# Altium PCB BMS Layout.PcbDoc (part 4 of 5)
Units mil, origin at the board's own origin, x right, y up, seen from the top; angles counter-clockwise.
Board outline 5576.78 x 4051.82 mil, 6 copper layers (Top Layer, GND1, Analog Signal, Power, GND2, Bottom Layer), stack 61.2 mil thick; 425 components, 206 nets, 1164 pads, 390 vias.
Unrouted connection lines stored in the file: 32.
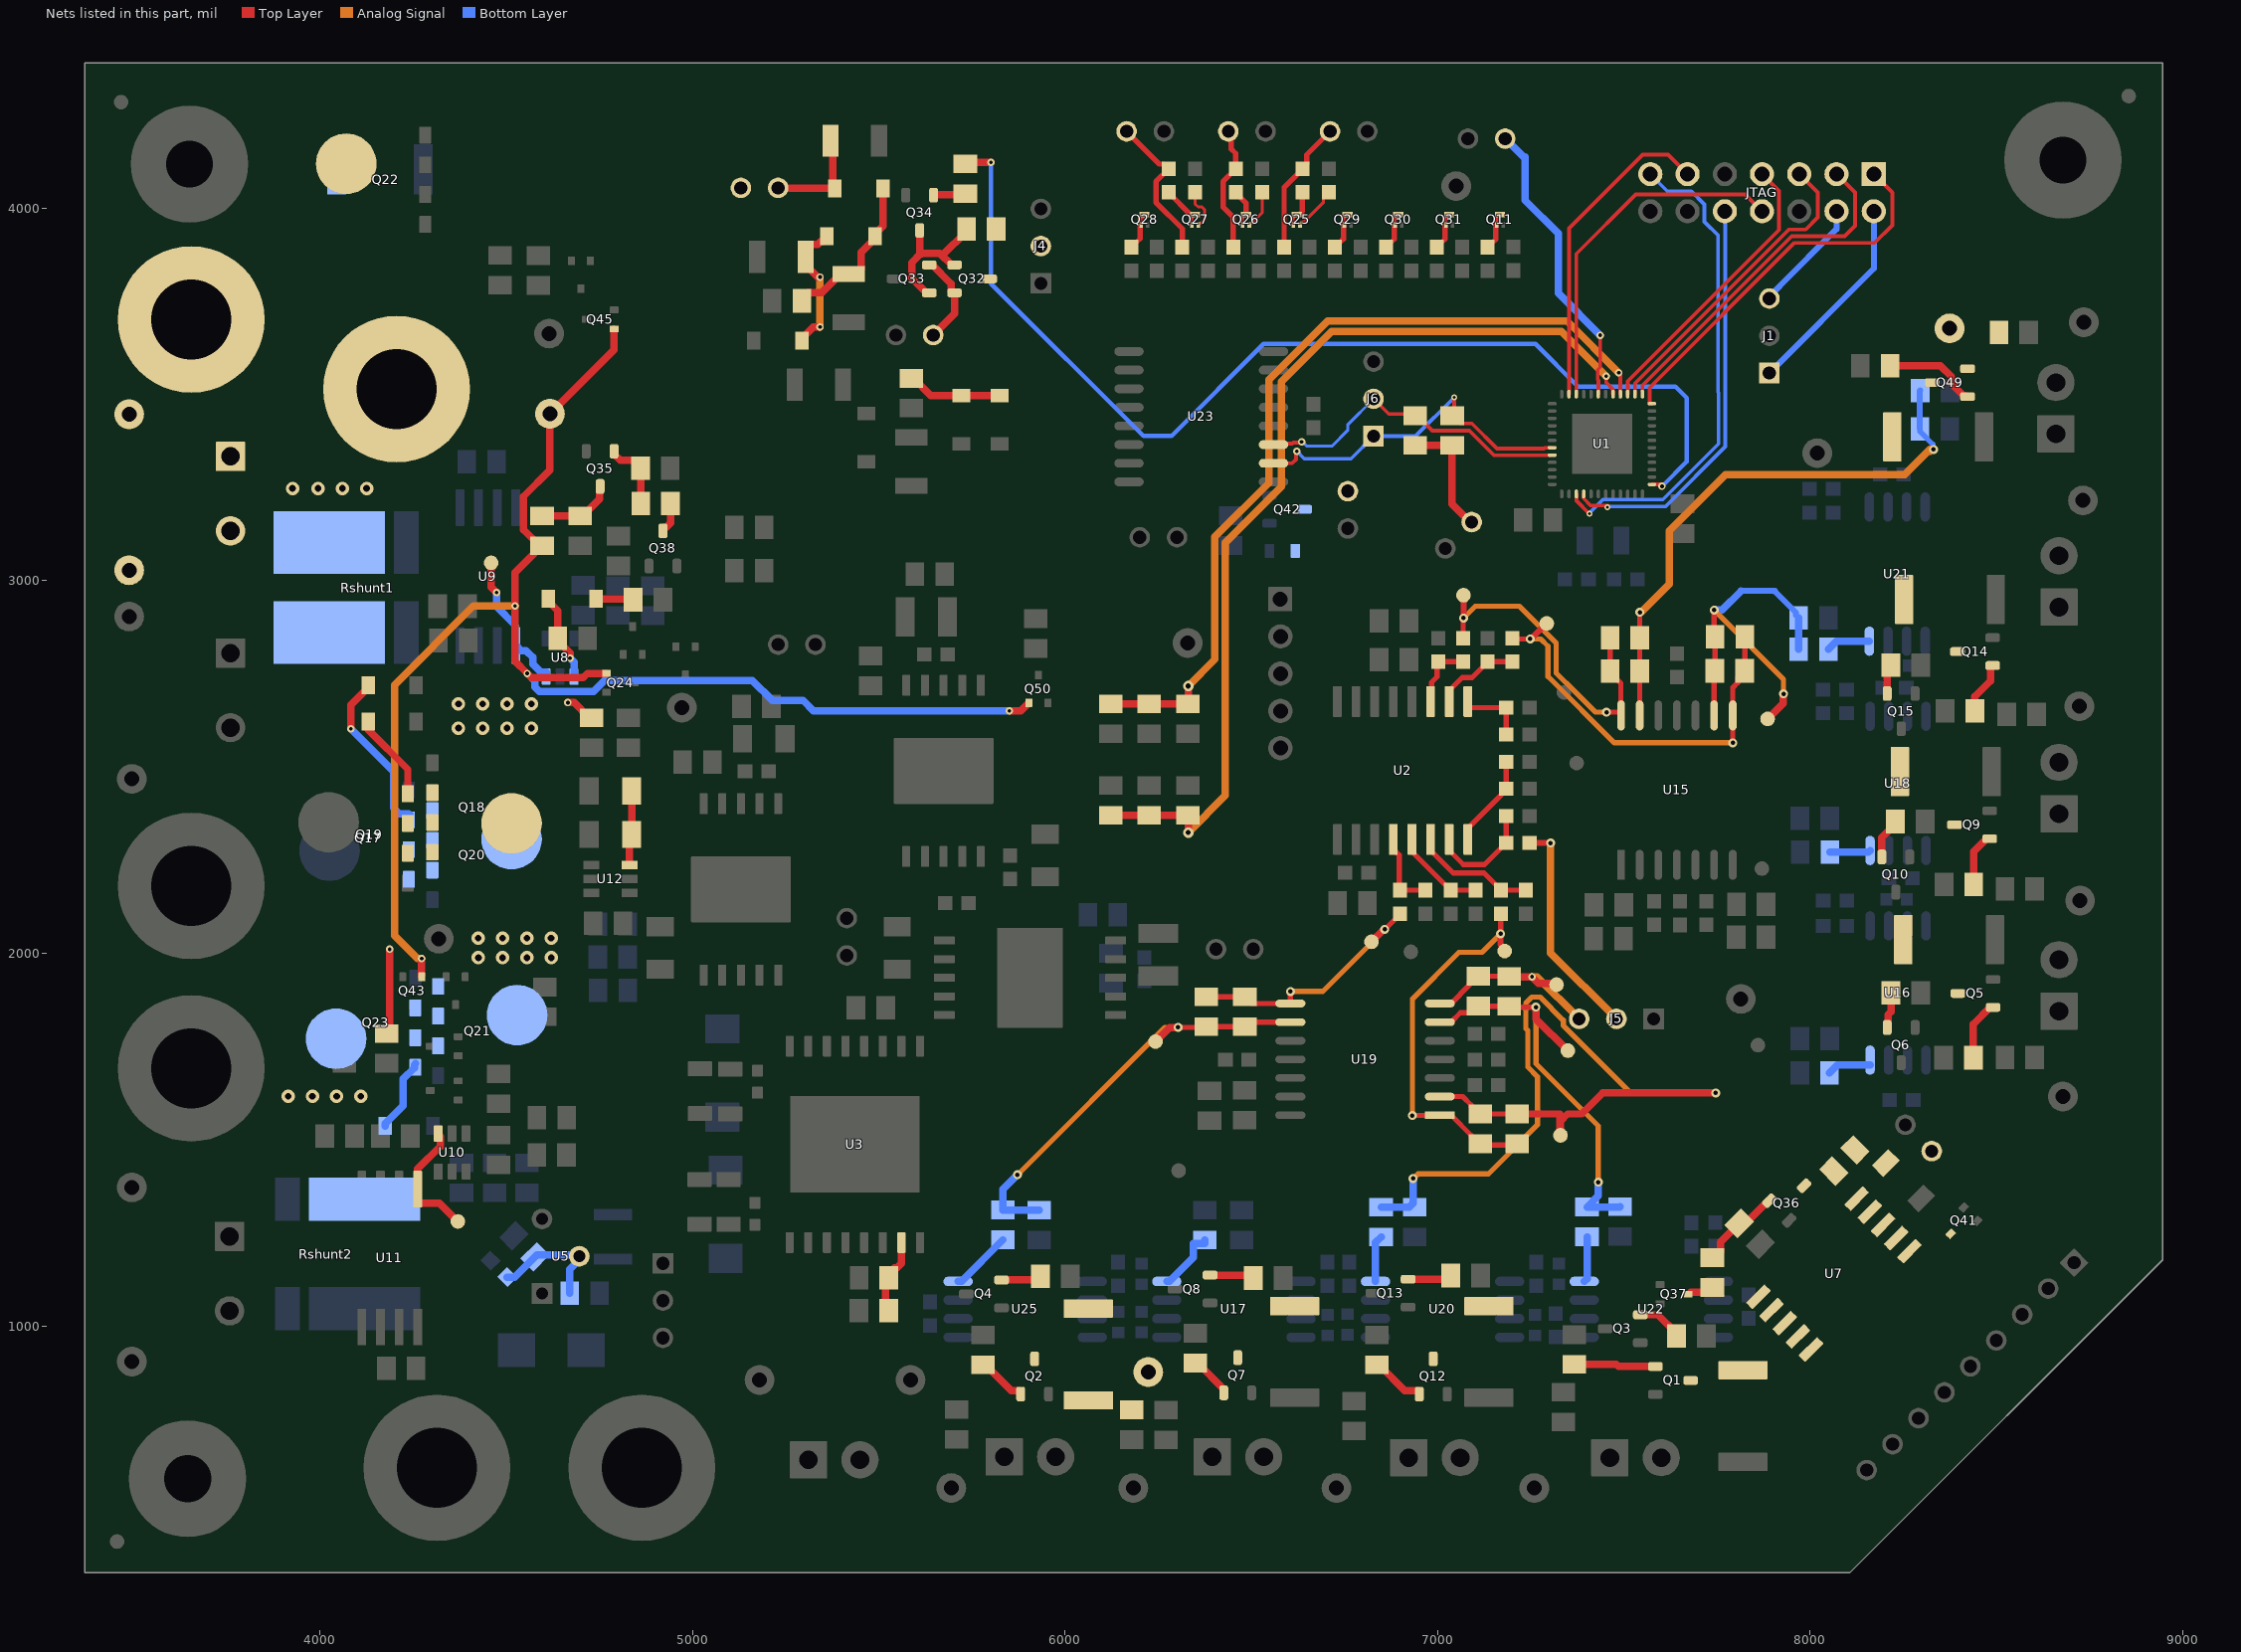
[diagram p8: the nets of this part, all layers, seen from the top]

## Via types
v1: diameter 20, hole 10, Top Layer to Bottom Layer, tented both sides, 113 vias
v2: diameter 24, hole 12, Top Layer to Bottom Layer, tented both sides, 103 vias
v3: diameter 19.68, hole 7.87, Top Layer to Bottom Layer, 93 vias
v4: diameter 36, hole 18, Top Layer to Bottom Layer, 46 vias
v5: diameter 36, hole 18, Top Layer to Bottom Layer, tented both sides, 12 vias
v6: diameter 16, hole 8, Top Layer to Bottom Layer, tented both sides, 10 vias
v7: diameter 26, hole 13, Top Layer to Bottom Layer, tented both sides, 7 vias
v8: diameter 32, hole 16, Top Layer to Bottom Layer, tented both sides, 3 vias
v9: diameter 28, hole 14, Top Layer to Bottom Layer, tented both sides, 2 vias
v10: diameter 20, hole 12, Top Layer to Bottom Layer, tented both sides, 1 vias

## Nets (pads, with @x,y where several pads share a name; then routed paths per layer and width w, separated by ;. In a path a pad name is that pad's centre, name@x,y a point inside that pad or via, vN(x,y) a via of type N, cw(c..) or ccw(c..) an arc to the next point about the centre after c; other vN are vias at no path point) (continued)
NetC93_1: C93.1 R93.2 R95.1 TP14.1 U19.1 | length 1047.4
  Top Layer w14: v2(6932.25,1564.33) 6932.71,1564.8 7005.32,1564.8 U19.1@7005.79,1565.26 7035.92,1565.26 7090.41,1510.77 7090.41,1506.75 7108.41,1488.75 C93.1@7114.91,1488.75 7118.22,1485.45 7213.11,1485.45 R93.2@7213.11,1488.75 ; v2(7168.77,2052.18) 7169.25,2052.66 7169.25,2105.82 R95.1@7169.74,2106.31
  Top Layer w16: v2(7168.77,2052.18) 7168.77,2023.43 7179.87,2012.33 TP14.1@7179.87,2006
  Analog Signal w14: v2(6932.25,1564.33) 6932.25,1877.57 7057.17,2002.49 7119.08,2002.49 v2(7168.77,2052.18)
NetC93_2: C93.2 R93.1 R94.2 R96.2 TP29.1 U19.2 | length 2409.5
  Top Layer w14: U19.2@7005.79,1615.26 7067.25,1615.26 7090.41,1592.1 7090.41,1586.75 7108.41,1568.75 C93.2@7114.91,1568.75 R93.1@7213.11,1568.75
  Top Layer w20: R93.1@7213.11,1568.75 7328.41,1568.75 7328.41,1512.44 TP29.1@7329.65,1511.2 7329.65,1549.65 7348.76,1568.75 7387.21,1568.75 7443.48,1625.03 v2(7746.06,1625.03)
  Analog Signal w14: v2(6933.89,1395.49) 6934.86,1395.49 6947.09,1407.71 7135.75,1407.71 7267.69,1539.65 7267.69,1669.04 7241.79,1694.93 7241.79,1792.6 7236.79,1797.6 7236.79,1866.44 7252.61,1882.26 7274.98,1882.26 7337.09,1820.14 7337.09,1806.17 7518.24,1625.03 v2(7746.06,1625.03)
  Bottom Layer w20: R94.2@6848.2,1318.58 6923.76,1318.58 6933.89,1328.7 v2(6933.89,1395.49)
NetC97_1: C97.1 R98.2 R99.1 TP15.1 U15.8 | length 1115.2
  Top Layer w14: R99.1@7200.33,2845.49 7202.1,2843.71 v2(7248.26,2843.71) ; v2(7792.09,2564.98) U15.8@7792.08,2638.49 7792.08,2713.16 7805.66,2726.75 7805.66,2740.11 C97.1@7823.66,2758.11 7824.55,2759 R98.2@7824.55,2849.79
  Top Layer w16: v2(7248.26,2843.71) 7250.52,2843.71 TP15.1@7292.41,2885.6
  Analog Signal w14: v2(7248.26,2843.71) 7276.52,2843.71 7296.18,2824.05 7296.18,2743.05 7474.26,2564.98 v2(7792.09,2564.98)
NetC97_2: C97.2 R97.2 R98.1 R100.2 TP30.1 U15.9 | length 1029.8
  Top Layer w14: U15.9@7742.08,2638.49 7742.08,2756.53 C97.2@7743.66,2758.11 7744.55,2759 R98.1@7744.55,2849.79 7742.08,2852.26 v2(7742.08,2921.4)
  Top Layer w20: TP30.1@7885.52,2629 7927.4,2670.89 7927.4,2695.63 v2(7928.17,2696.4)
  Analog Signal w14: v2(7742.08,2921.4) 7928.17,2735.31 v2(7928.17,2696.4)
  Bottom Layer w16: 7814.55,2972.7 7905.32,2972.7 7905.32,2970.86 7962.05,2914.13 R100.2@7962.05,2907.63
  Bottom Layer w20: v2(7742.08,2921.4) 7763.25,2921.4 7814.55,2972.7 ; R97.2@7968.59,2816.14 7968.59,2900.05 R100.2@7969.11,2900.57
NetC101_2: C101.2 R101.2 R102.1 R104.2 TP40.1 U19.6 | length 1134.3
  Top Layer w14: U19.6@7005.79,1815.26 7035.92,1815.26 7061.23,1840.57 7091.32,1840.57 C101.2@7109.32,1858.57 7110.09,1857.8 R102.1@7192.33,1857.8 7194.86,1855.26 v2(7263.79,1855.26)
  Top Layer w20: v2(7263.79,1855.26) 7264.56,1854.5 7264.56,1823.47 TP40.1@7349.43,1738.61
  Analog Signal w14: v2(7263.79,1855.26) 7263.79,1704.04 7430.98,1536.86 v2(7430.98,1385.64)
  Bottom Layer w20: R101.2@7400.92,1319 7430.98,1349.07 v2(7430.98,1385.64) ; R101.2@7403.03,1319 7488.62,1319 R104.2@7489.53,1319.92
NetC102_1: C102.1 R2.2 R3.1 TP17.1 U19.8 | length 697.7
  Top Layer w14: R2.2@6378.86,1882.9 C102.1@6482.36,1882.9 6499.99,1865.26 U19.8@6604.71,1865.26 6604.76,1865.32 v2(6604.76,1897.66) ; v2(6858.16,2064) 6899.49,2105.32 R3.1@6899.49,2106.31
  Top Layer w20: TP17.1@6822.43,2030.79 6854.87,2063.23 6857.4,2063.23 v2(6858.16,2064)
  Analog Signal w14: v2(6604.76,1897.66) 6691.83,1897.66 v2(6858.16,2064) v2@6857.21,2064
NetC102_2: C102.2 R2.1 R4.2 R5.2 TP25.1 U19.9 | length 1186
  Top Layer w14: v2(6303.35,1801.07) 6377.04,1801.07 R2.1@6378.86,1802.9 C102.2@6482.36,1802.9 6494.72,1815.26 U19.9@6604.71,1815.26
  Top Layer w20: TP25.1@6242.76,1763.11 6279.96,1800.31 6302.59,1800.31 v2(6303.35,1801.07)
  Analog Signal w14: v2(5872.12,1405.33) 6267.87,1801.07 v2(6303.35,1801.07)
  Bottom Layer w20: v2(5872.12,1405.33) 5833.52,1366.73 R4.2@5833.52,1311.03 5929.64,1311.03 R5.2@5930.29,1310.39
NetC106_1: C106.1 R105.2 R107.1 TP18.1 U15.14 | length 929.2
  Top Layer w14: R107.1@7067.88,2845.49 7068.61,2846.22 7068.61,2899.45 v2(7069.35,2900.18) ; v2(7453.25,2647.01) 7489,2647.01 7491.78,2649.8 7491.78,2670.72 7491.49,2671.01 7491.49,2724.58 7483.29,2732.78 7480.59,2732.78 7462.59,2750.78 R105.2@7462.59,2757.28 C106.1@7462.59,2846.85
  Top Layer w16: v2(7069.35,2900.18) TP18.1@7069.35,2961.2
  Analog Signal w14: v2(7069.35,2900.18) 7101.08,2931.91 7219.42,2931.91 7318.18,2833.16 7318.18,2752.17 7368.65,2701.7 7423.33,2647.01 v2(7453.25,2647.01)
NetC106_2: C106.2 R105.1 R106.2 R108.2 U15.13 | length 1514.7
  Top Layer w14: U15.13@7542.08,2638.49 7542.08,2756.77 R105.1@7542.59,2757.28 C106.2@7542.59,2846.85 v2(7542.59,2915.12)
  Analog Signal w14: v2@8322.67,3344.08 v2(8330.87,3352.28)
  Analog Signal w20: v2(7542.59,2915.12) 7545.7,2915.12 7622.08,2991.51 7622.08,3133.43 7772.94,3284.29 8253.13,3284.29 8321.13,3352.28 v2(8330.87,3352.28)
  Bottom Layer w14: R106.2@8294.23,3407.51 8294.23,3401.01 8328.96,3366.29 8328.96,3354.2 v2(8330.87,3352.28)
  Bottom Layer w16: R106.2@8294.23,3407.51 8294.23,3509.77 R108.2@8294.97,3510.51
NetC111_1: C111.1 R103.2 U2.7 | length 296.3
  Top Layer w14: U2.7@7030.9,2305.8 7030.9,2276.27 7035.71,2271.46 7068.91,2238.26 7125.9,2238.26 7171.13,2283.49 7171.13,2284.48 7182.83,2296.18 R103.2@7183.81,2296.18 C111.1@7183.81,2368.79
  Top Layer w20: R103.2@7183.81,2296.18 R103.2@7184.8,2296.18
NetC112_1: C112.1 J_2V5.2 R18.1 U7.10
NetC124_1: C124.1 D7.2 D10.1 | length 371.8
  Top Layer w20: D10.1@5293.78,3644.83 5293.78,3650.83 5324.2,3681.25 5342.03,3681.25 v1(5342.34,3680.94) ; v1(5342.34,3815.11) 5335.99,3815.11 5303.47,3847.63 C124.1@5303.47,3869.28 5303.47,3890.93 5315.13,3902.59 5336.78,3902.59 5344.58,3910.38 5352.79,3910.38 5360.8,3918.39 D7.2@5360.8,3924.4
  Analog Signal w20: v1(5342.34,3680.94) v1(5342.34,3815.11)
NetC125_1: C125.1 D7.1 D8.2 R22.1 | length 439.7
  Top Layer w20: R22.1@5293.78,3751.17 5293.78,3757.67 5308.78,3772.67 5346.91,3772.67 5397.66,3823.42 C125.1@5419.32,3823.42 5440.97,3823.42 5452.62,3835.07 5452.62,3881.28 5489.74,3918.39 D7.1@5489.74,3924.4 5489.74,3930.4 5510.97,3951.63 D8.2@5510.97,4053.19
NetC126_1: C126.1 D8.1 J_pump.1 | length 284.5
  Top Layer w20: J_pump.1@5229.78,4054.49 5230.43,4053.84 D8.1@5381.38,4053.84 ; C126.1@5370.5,4181.06 5376.27,4175.29 5376.27,4058.95 D8.1@5381.38,4053.84 ; D8.1@5382.03,4053.19 D8.1@5381.38,4053.84
NetC164_1: C164.1 J_3V3_2.1 Q42.3
NetD1_1: D1.1 D2.1 R119.1 | length 256.3
  Top Layer w20: R119.1@5586.93,3543.21 5593.43,3543.21 5639.7,3496.94 D2.1@5721.53,3496.94 D1.1@5824.02,3496.94
NetD3_1: D3.1 R50.1 | length 100.1
  Top Layer w20: D3.1@4741.53,2951.16 4838.69,2951.16 R50.1@4840.75,2949.1
NetD3_2: D3.2 R49.1 U8.1 | length 237.3
  Top Layer w20: D3.2@4612.6,2951.16 4612.6,2945.16 4638.15,2919.61 4638.15,2838.77 4671.23,2805.69 v1(4671.23,2792.34)
  Bottom Layer w20: v1(4671.23,2792.34) 4682.03,2781.53 U8.1@4682.03,2742.6
NetD4_2: D4.2 Q17.2 Q17.3 Q17.4 Q18.2 Q18.3 Q18.4 | length 237.7
  Top Layer w20: D4.2@4129.63,2622.2 4129.63,2600.01 4235.89,2493.75 Q17.4@4235.89,2428.48
NetD5_2: D5.2 Q19.2 Q19.3 Q19.4 Q20.2 Q20.3 Q20.4 | length 456.8
  Top Layer w20: v1(4082.85,2602.4) 4082.85,2667.12 4129.63,2713.91 D5.2@4129.63,2719.91
  Bottom Layer w20: v1(4082.85,2602.4) 4197.66,2487.59 4197.66,2389.88 4212.63,2374.91 4238.05,2374.91 4241.83,2371.13 Q19.2@4241.83,2363.25
NetD6_2: D6.2 Q21.2 Q21.3 Q21.4 Q23.2 Q23.3 Q23.4 | length 201.9
  Bottom Layer w20: D6.2@4174.77,1536.45 4174.77,1542.45 4223.48,1591.16 4223.48,1662.75 4253.32,1692.59 4253.32,1700.46 Q23.4@4257.1,1704.24
NetI2C_pull_2: I2C_pull.2 R110.2 R111.2 | length 328.1
  Top Layer w20: R110.2@6939.43,3363.11 R111.2@7038.95,3363.11 7038.95,3205.5 I2C_pull.2@7089.14,3155.3
NetJ4_2: J4.2 Q32.3 R120.2
NetJ5_2: J5.2 R103.1 | length 604.1
  Top Layer w16: R103.1@7246.8,2296.18 7246.91,2296.08 7303.06,2296.08 v2(7303.16,2295.98) v2@7304.83,2297.65
  Analog Signal w20: v2(7303.16,2295.98) 7303.16,2000.29 J5.2@7479.65,1823.8
NetJ_heater_1: J_heater.1 U1.19 | length 797.7
  Top Layer w10: U1.19@7431.27,3500.71 7431.27,3537.79 7429.5,3539.57 7429.5,3566.13 7436.24,3572.87 v1(7436.24,3658.78)
  Bottom Layer w20: J_heater.1@7181.21,4186.51 7230.42,4137.3 7235.11,4137.3 7235.11,4020.92 7323.57,3932.46 7323.57,3771.45 v1(7436.24,3658.78)
NetJ_PWM_1: J_PWM.1 Q32.2 Q33.2 | length 248.2
  Top Layer w20: Q33.2@5635.4,3847.63 5643.27,3847.63 5693.57,3797.33 5693.57,3774.63 5695.38,3772.82 5701.44,3772.82 5703.26,3771.01 5703.26,3716.65 J_PWM.1@5646.01,3659.4
NetLoad_1: Load.1 LOAD_GND.1 Q22.5 R44.2 TP11.1
NetLoad_2: Load.2 Load_.1 Rshunt1.2 TP23.1
  other v4: 3926.42,3247.85 3994.98,3247.85 4060.11,3247.85 4125.25,3247.85
NetQ1_1: Q1.1 R60.1 | length 219.9
  Top Layer w20: R60.1@7366.67,896.36 7479.54,896.36 7485.08,890.82 Q1.1@7584.32,890.82
NetQ1_3: Q1.3 R26.2
NetQ2_1: Q2.1 R61.1 | length 138.4
  Top Layer w20: R61.1@5779.71,895.51 5786.21,895.51 5855.29,826.43 5879.01,826.43 5880.83,824.62 Q2.1@5880.83,816.75
NetQ2_3: Q2.3 R8.2
NetQ3_2: Q3.2 R14.2 | length 124.6
  Top Layer w20: Q3.2@7543.79,1029.51 7591.1,1029.51 7641.17,979.44 R14.2@7641.17,972.94
NetQ4_2: Q4.2 R25.2 | length 108.3
  Top Layer w20: Q4.2@5829.51,1123.11 5923.82,1123.11 R25.2@5933.68,1132.97
NetQ5_1: Q5.1 R64.1 | length 161.9
  Top Layer w20: R64.1@8437.92,1719.46 8437.92,1809.94 8482.83,1854.85 Q5.1@8490.7,1854.85
NetQ5_3: Q5.3 R32.2
NetQ6_2: Q6.2 R29.2 | length 97.1
  Top Layer w20: Q6.2@8206.61,1800.78 8208.43,1802.59 8208.43,1835.5 8216.46,1843.53 R29.2@8216.46,1893.8
NetQ7_1: Q7.1 R65.1 | length 115.4
  Top Layer w20: R65.1@6349.36,899.97 6355.86,899.97 6424.22,831.61 6424.22,821.92 Q7.1@6426.03,820.11
NetQ7_3: Q7.3 R27.2
NetQ8_2: Q8.2 R31.2 | length 119.4
  Top Layer w20: Q8.2@6389.05,1136.25 6497.18,1136.25 R31.2@6505.13,1128.31
NetQ9_1: Q9.1 R68.1 | length 145.1
  Top Layer w20: R68.1@8438.93,2184.68 8438.93,2272.82 8473.65,2307.55 Q9.1@8481.53,2307.55
NetQ9_3: Q9.3 R37.2
NetQ10_2: Q10.2 R35.2 | length 110
  Top Layer w20: Q10.2@8192.17,2258.58 8192.17,2310.67 8228.53,2347.03 R35.2@8228.53,2353.53
NetQ11_1: Q11.1 Q11.3 R6.1 | length 105.1
  Top Layer w14: R6.1@7134.38,3895.2 7134.38,3896.19 7146.08,3907.89 7147.06,3907.89 7156.14,3916.96 7156.14,3969.23 7160.42,3973.51 7160.42,3981.83 7161.3,3982.7 Q11.3@7167.2,3982.7
NetQ12_1: Q12.1 R70.1 | length 151.7
  Top Layer w20: R70.1@6836.35,895.51 6842.85,895.51 6911.92,826.43 6948.98,826.43 6950.79,824.62 Q12.1@6950.79,816.75
NetQ12_3: Q12.3 R33.2
NetQ13_2: Q13.2 R38.2 | length 118.8
  Top Layer w20: Q13.2@6920.58,1125.09 7025.48,1125.09 R38.2@7035.32,1134.94
NetQ14_1: Q14.1 R72.1 | length 143.7
  Top Layer w20: R72.1@8441.9,2650.99 8441.9,2689.1 8483.38,2730.58 8483.38,2770.58 8485.19,2772.39 Q14.1@8489.53,2772.39
NetQ14_3: Q14.3 R40.2
NetQ15_2: Q15.2 R39.2 | length 80.2
  Top Layer w20: Q15.2@8206.61,2697.03 8206.61,2763.38 R39.2@8216.4,2773.17
NetQ18_5: Q18.5 Q20.5 Q21.5 Rshunt1.1
  other v4: 4425.26,1988.08 4490.4,1988.08 4555.53,1988.08 4620.66,1988.08 4425.02,2040.39 4490.15,2040.39 4555.28,2040.39 4620.42,2040.39 4371.97,2604.28 4437.1,2604.28 4502.23,2604.28 4567.37,2604.28 4371.97,2669.41 4437.1,2669.41 4502.23,2669.41 4567.37,2669.41
NetQ23_5: Q23.5 Rshunt2.1
  other v4: 3914.6,1616.21 3979.74,1616.21 4044.87,1616.21 4110,1616.21
NetQ24_1: Q24.1 Q43.1 Q45.1 Q50.1 R51.2 TP20.1 | length 3973.6
  Top Layer w20: Q43.1@4273.17,1938.57 v1(4273.17,1985.89) ; R51.2@4596.35,3094.01 R51.2@4589.85,3094.01 ; Q24.1@4769.03,2751.41 4717.81,2751.41 4706.24,2739.84 4567.83,2739.84 v1(4556.26,2751.41) 4523.88,2783.78 v1(4523.88,2932.1) 4523.88,3021.54 4574.85,3072.51 4574.85,3079.01 R51.2@4589.85,3094.01 ; Q45.1@4789.55,3675.71 4789.55,3620.25 TP20.1@4617.24,3447.94 4617.24,3296.97 4546.85,3226.58 4546.85,3137.01 R51.2@4589.85,3094.01 ; v1(5850.52,2650.6) 5881.28,2650.6 5900.96,2670.29 5902.03,2670.29 5902.77,2671.03 Q50.1@5902.77,2672.1
  Analog Signal w20: v1(4273.17,1985.89) 4261.82,1985.89 4200.02,2047.69 4200.02,2720.26 4411.86,2932.1 v1(4523.88,2932.1)
  Bottom Layer w20: v1(4556.26,2751.41) 4577.42,2730.25 4577.42,2714.67 4589.14,2702.95 4734.61,2702.95 4763.79,2732.14 5160.58,2732.14 5214.61,2678.1 5297.06,2678.1 5324.56,2650.6 v1(5850.52,2650.6)
NetQ25_1: Q25.1 Q25.3 R128.1 | length 104
  Top Layer w8: Q25.1@6612.98,3955.14 6612.98,3978.83 6616.86,3982.7 Q25.3@6621.84,3982.7
  Top Layer w14: Q25.3@6621.84,3982.7 6627.75,3982.7 6636.86,3991.81 R128.1@6636.86,4042.84
NetQ25_2: Q25.2 R129.1 | length 122.9
  Top Layer w8: Q25.2@6630.7,3955.14 6630.7,3958.1 6635.43,3962.83 6640.59,3962.83 6693.66,4015.89 6693.66,4028.14 R129.1@6708.36,4042.84
NetQ26_1: Q26.1 Q26.3 R130.1 | length 105.7
  Top Layer w8: Q26.1@6476.64,3955.14 6476.64,3978.83 6480.52,3982.7 Q26.3@6485.5,3982.7
  Top Layer w14: R130.1@6457.84,4042.84 6457.84,4041.86 6485.5,4014.2 Q26.3@6485.5,3982.7
NetQ26_2: Q26.2 R131.1 | length 105.2
  Top Layer w8: Q26.2@6494.36,3955.14 6494.36,3958.1 6495.28,3959.02 6500.44,3959.02 6529.34,3987.92 R131.1@6529.34,4042.84
NetQ27_1: Q27.1 Q27.3 R132.1 | length 126.2
  Top Layer w8: Q27.1@6340.3,3955.14 6340.3,3978.83 6345.05,3983.58 Q27.3@6348.28,3983.58
  Top Layer w14: R132.1@6277.66,4042.84 6277.66,4041.86 6335.94,3983.58 Q27.3@6345.05,3983.58
NetQ27_2: Q27.2 R133.1 | length 114.4
  Top Layer w8: R133.1@6349.16,4042.84 6349.16,4011.16 6356.96,4003.35 6367.13,4003.35 6374.94,3995.55 6374.94,3969.86 6364.1,3959.02 6358.94,3959.02 6358.02,3958.1 Q27.2@6358.02,3955.14
NetQ28_1: Q28.1 Q28.3 R115.1 | length 105.9
  Top Layer w14: R115.1@6178.16,3895.2 6178.16,3896.19 6189.86,3907.89 6190.84,3907.89 6201.75,3918.8 6201.75,3969.23 6206.04,3973.51 6206.04,3981.83 6206.91,3982.7 Q28.3@6212.82,3982.7
NetQ29_1: Q29.1 Q29.3 R116.1 | length 105.4
  Top Layer w14: R116.1@6724.61,3895.2 6724.61,3896.19 6736.31,3907.89 6737.3,3907.89 6747.12,3917.71 6747.12,3977.54 6752.28,3982.7 Q29.3@6758.18,3982.7
NetQ30_1: Q30.1 Q30.3 R117.1 | length 105.3
  Top Layer w14: R117.1@6861.22,3895.2 6861.22,3896.19 6872.93,3907.89 6873.91,3907.89 6883.46,3917.44 6883.46,3977.54 6888.62,3982.7 Q30.3@6894.52,3982.7
NetQ31_1: Q31.1 Q31.3 R118.1 | length 105.2
  Top Layer w14: R118.1@6997.84,3895.2 6997.84,3896.19 7009.54,3907.89 7010.52,3907.89 7019.8,3917.16 7019.8,3969.23 7024.08,3973.51 7024.08,3981.83 7024.96,3982.7 Q31.3@7030.86,3982.7
NetQ32_1: Q32.1 Q33.1 Q34.3 R120.1 | length 406.3
  Top Layer w20: Q34.3@5609.52,3940.36 5609.52,3879.63 5611.72,3877.44 ; Q33.1@5635.4,3772.82 5627.53,3772.82 5588.16,3812.19 5588.16,3853.87 5611.72,3877.44 ; 5670.16,3872.85 5735.3,3937.99 R120.1@5735.3,3944.49 ; Q32.1@5703.26,3847.63 5695.38,3847.63 5663.89,3879.12 5616.99,3879.12 5615.3,3877.44 5611.72,3877.44
NetQ34_1: Q34.1 R1.1 | length 87
  Top Layer w20: Q34.1@5646.93,4034.85 5646.93,4035.01 5648.74,4036.82 5730.27,4036.82 R1.1@5732.23,4038.78
NetQ35_1: Q35.1 R47.1 R48.2 | length 192.8
  Top Layer w20: Q35.1@4789.55,3347.64 4789.55,3339.77 4805.99,3323.33 4845.34,3323.33 4860.34,3308.33 R47.1@4860.34,3301.83 4860.66,3301.51 4860.66,3207.77 R48.2@4860.97,3207.45
NetQ35_3: Q35.3 R51.1 R53.2 | length 207.2
  Top Layer w20: R51.1@4596.35,3174.01 4704.88,3174.01 4750.34,3219.47 4750.34,3251.34 Q35.3@4752.15,3253.15
NetQ36_1: Q36.1 R139.1 R143.2 | length 231.8
  Top Layer w20: R143.2@7737.31,1183.09 7743.81,1183.09 7758.81,1198.09 7758.81,1224.58 R139.1@7809.54,1275.31 7827.22,1275.31 7887.77,1335.87 Q36.1@7890.33,1335.87
NetQ36_3: Q36.3 R18.2
NetQ37_3: Q37.3 R143.1 | length 63.7
  Top Layer w20: Q37.3@7678.65,1090.81 7725.03,1090.81 R143.1@7737.31,1103.09
NetQ38_3: Q38.3 R48.1 | length 85.8
  Top Layer w20: Q38.3@4920.66,3134.01 4920.66,3141.88 4922.47,3143.69 4929.26,3143.69 4940.97,3155.41 R48.1@4940.97,3207.45
NetQ41_3: Q41.3 U7.1 U7.2 U7.3 U7.4 U7.5 U7.6 U7.7 U7.8 U7.9
NetQ49_1: Q49.1 R75.1 | length 252.4
  Top Layer w20: R75.1@8214.59,3577.15 8349.61,3577.15 8379.23,3547.53 8379.23,3529.4 8412.42,3496.2 8420.3,3496.2 Q49.1@8422.11,3494.39
NetQ49_2: Q49.2 R67.1 TP43.1
NetQ49_3: Q49.3 R43.1
NetR4_1: R4.1 U25.4 | length 167
  Bottom Layer w20: U25.4@5712.82,1119.19 5721.68,1119.19 R4.1@5833.52,1231.03
NetR8_1: R8.1 R66.1 TP41.1
NetR10_1: R10.1 R15.2 U3.7 | length 204
  Top Layer w20: R15.2@5518.23,1041.02 5518.36,1041.15 5518.36,1125.35 5518.48,1125.48 5518.48,1131.98 5542.55,1156.05 5549.05,1156.05 5560.77,1167.76 U3.7@5560.77,1223.58
NetR55_1: R55.1 R58.2 U12.3 | length 201.2
  Top Layer w20: U12.3@4830.89,2236.7 4830.89,2312.89 R55.1@4836.8,2318.8 R58.2@4836.8,2435.48
NetR85_1: R85.1 U16.4 | length 117.4
  Bottom Layer w20: R85.1@8051.84,1678.79 8072.77,1699.72 U16.4@8160.57,1699.72
NetR87_1: R87.1 U17.4 | length 175.9
  Bottom Layer w20: U17.4@6272.96,1119.19 6280.3,1119.19 6344.37,1183.25 6344.37,1221.44 6375.2,1221.44 R87.1@6375.2,1230.39
NetR89_1: R89.1 U18.4 | length 109.8
  Bottom Layer w20: R89.1@8052.7,2271.2 8155.87,2271.2 U18.4@8160.57,2275.9
NetR94_1: R94.1 U20.4 | length 125.6
  Bottom Layer w20: U20.4@6833.1,1119.19 6833.1,1223.47 R94.1@6848.2,1238.58
NetR97_1: R97.1 U21.4 | length 118.9
  Bottom Layer w20: R97.1@8048.59,2816.14 8070.22,2837.77 U21.4@8158.53,2837.77
NetR101_1: R101.1 U22.4 | length 123
  Bottom Layer w20: U22.4@7393.24,1119.19 7400.92,1126.87 R101.1@7400.92,1239
NetR112_1: R112.1 R128.2 Sensor1.2 | length 362
  Top Layer w14: R112.1@6588,3895.2 6588,4055.99 6636.86,4104.85 R128.2@6636.86,4105.83 6648.56,4117.53 6648.56,4143.59 Sensor1.2@6711.17,4206.2
NetR113_1: R113.1 R130.2 Sensor2.2 | length 344.4
  Top Layer w14: Sensor2.2@6438.17,4206.2 6446.04,4198.33 6446.04,4158.76 6457.84,4146.96 R130.2@6457.84,4105.83 6457.84,4104.85 6424.14,4071.15 6424.14,4003.14 6451.38,3975.89 R113.1@6451.38,3895.2
NetR114_1: R114.1 R132.2 Sensor3.2 | length 408.6
  Top Layer w14: Sensor3.2@6165.18,4206.2 6252.86,4118.52 6265.96,4118.52 6277.66,4106.82 R132.2@6277.66,4105.83 6277.66,4104.85 6243.96,4071.15 6243.96,4015.53 6314.77,3944.71 R114.1@6314.77,3895.2
NetTP45_1: TP45.1 U8.3 U9.5 | length 382.8
  Top Layer w20: TP45.1@4459.69,3048.05 4459.69,2982.82 v1(4474.33,2968.17)
  Bottom Layer w20: v1(4474.33,2968.17) 4474.33,2930.43 4523.93,2880.84 4523.93,2828.07 U9.5@4525.74,2826.26 4539.59,2812.41 4553.16,2812.41 4571.41,2794.16 4571.41,2775.85 4593.01,2754.26 4607.23,2754.26 U8.3@4607.23,2742.6
NetTP46_1: TP46.1 U10.3 U11.5 | length 331.1
  Top Layer w20: U10.3@4323.01,1508.3 4323.01,1481.94 4262.43,1421.35 U11.5@4262.43,1366.74 4262.43,1331.34 4264.24,1329.53 4320.94,1329.53 TP46.1@4370.31,1280.16
nRST: JTAG.11 U1.23 | length 866.8
  Top Layer w10: U1.23@7352.53,3500.71 7352.53,3946.03 7550.09,4143.59 7618.53,4143.59 JTAG.11@7670.58,4091.54
pump: J_pump.2 R41.1 R42.1 | length 309.9
  Top Layer w20: R41.1@4179.67,1784.68 4187.43,1792.43 v1(4187.43,2010.78) ; v1(4665.59,2672.83) 4681.97,2672.83 4722.76,2632.04 R42.1@4729.26,2632.04
PWM_10k: R1.2 U1.1 | length 2889.1
  Top Layer w10: U1.1@7574.97,3258.58 7597.28,3258.58 v1(7602.32,3253.54)
  Top Layer w20: R1.2@5732.23,4118.78 5736.08,4122.63 v1(5801.32,4122.63)
  Bottom Layer w12: v1(5801.32,4122.63) 5801.32,3797.68 6210.75,3388.25 6285.12,3388.25 6532.35,3635.48 7262.48,3635.48 7376.86,3521.09 7638.38,3521.09 7668.66,3490.81 7668.66,3319.89 v1(7602.32,3253.54)
TCK: JTAG.7 U1.15 | length 777.9
  Top Layer w10: U1.15@7510.01,3500.71 7510.01,3535.65 7916.06,3941.69 7916.06,4046.06 JTAG.7@7870.58,4091.54
TDI: JTAG.3 U1.13 | length 924.1
  Top Layer w10: U1.13@7549.38,3507.52 7549.38,3524.11 7950.3,3925.02 8092.19,3925.02 8120.15,3952.98 8120.15,4041.97 JTAG.3@8070.58,4091.54
TDO: JTAG.1 U1.12 | length 1038.9
  Top Layer w10: U1.12@7574.97,3475.12 7569.15,3475.12 7568.88,3475.39 7568.88,3518.15 7957.76,3907.02 8173.17,3907.02 8220.28,3954.13 8220.28,4041.84 JTAG.1@8170.58,4091.54
TEMP_SCL: J6.2 R110.1 U1.32 U23.11 | length 873.5
  Top Layer w10: U23.11@6559.38,3365.3 6561.98,3367.91 6609.5,3367.91 6612.31,3370.72 6632.73,3370.72 v1(6634.64,3372.63) ; J6.2@6827.93,3488.25 6828.33,3488.25 6868.83,3447.75 6934.79,3447.75 R110.1@6939.43,3443.11 6945.93,3443.11 6985.93,3403.11 7085.11,3403.11 7151.47,3336.75 7292.29,3336.75 7292.59,3337.04 U1.32@7300.44,3337.04
  Bottom Layer w8: v1(6634.64,3372.63) 6637.88,3372.63 6649.45,3361.06 6716.09,3361.06 6758.18,3403.15 6758.18,3418.5 J6.2@6827.93,3488.25
TEMP_SDA: J6.1 R111.1 U1.31 U23.10 | length 944.1
  Top Layer w10: U23.10@6559.38,3315.3 6609.6,3315.3 6619.93,3325.63 6619.93,3345.81 v1(6621.84,3347.72) ; v6(7044.15,3492.84) 7044.15,3448.32 R111.1@7038.95,3443.11 7059.95,3422.11 7091.56,3422.11 7158.93,3354.75 7284.83,3354.75 7286.81,3356.73 7306.98,3356.73 U1.31@7307.26,3357.01
  Bottom Layer w10: v1(6621.84,3347.72) 6642.02,3327.55 6767.22,3327.55 J6.1@6827.93,3388.25 6940.6,3388.25 v6@7044.15,3491.8
TEST: JTAG.8 U1.22 | length 960.1
  Top Layer w10: U1.22@7372.22,3500.71 7372.22,3877.56 7531.67,4037.02 7825.1,4037.02 JTAG.8@7870.58,3991.54
TMS: JTAG.5 U1.14 | length 840.7
  Top Layer w10: U1.14@7529.7,3500.71 7529.7,3529.88 7942.84,3943.02 7987.78,3943.02 8020.02,3975.26 8020.02,4042.1 JTAG.5@7970.58,4091.54
U5_ADJ: C15.2 R12.1 R17.2 U5.2 | length 330.5
  Bottom Layer w20: C15.2@4502.61,1130.72 4503.31,1130.03 4521.94,1130.03 R12.1@4577.22,1185.32 4581.82,1189.91 4693.2,1189.91 U5.2@4696.26,1186.85 4696.26,1177.35 4670.38,1151.47 R17.2@4670.38,1087.09
UART_CTS: JTAG.10 U1.40 | length 1103.9
  Top Layer w10: U1.40@7391.9,3232.99 7391.9,3220.52 7410.42,3202 7450.66,3202 v6(7455.66,3196.99) ; v6@7455.66,3202 v6@7456.61,3202
  Bottom Layer w10: v6(7455.66,3196.99) 7458.1,3199.43 7611.43,3199.43 7772.09,3360.09 7772.09,3991.54 JTAG.10@7770.58,3991.54
UART_RTS: JTAG.13 U1.39 | length 1331.7
  Top Layer w10: U1.39@7372.22,3232.99 7372.49,3232.71 7372.49,3214.48 7406.84,3180.13 v6(7406.84,3179.73)
  Bottom Layer w10: v6(7406.84,3179.73) 7406.84,3181.35 7409.84,3184.35 7409.84,3184.65 7443.19,3217.99 7464.36,3217.99 7464.59,3217.77 7604.31,3217.77 7754.09,3367.54 7754.09,3504.89 7752.58,3506.4 7752.58,3927.22 7716.06,3963.74 7716.06,4010.38 7680.74,4045.7 7616.42,4045.7 JTAG.13@7570.58,4091.54
V_Batt_Sense: C122.1 R124.1 R141.2 U1.16 | length 2289.2
  Top Layer w10: v1(7486.04,3558.54) 7490.33,3554.25 U1.16@7490.33,3500.71
  Top Layer w20: R124.1@6122.28,2669.04 R141.2@6225.76,2669.04 C122.1@6329.24,2669.04 6330.47,2670.27 v9(6330.47,2717.28)
  Analog Signal w20: v9(6330.47,2717.28) 6402.03,2788.85 6402.03,3117.97 6546.69,3262.63 6546.69,3539.6 6704.2,3697.11 7347.47,3697.11 v1(7486.04,3558.54)
V_Charger_Sense: C123.1 R140.1 R142.2 U1.17 | length 2600.5
  Top Layer w10: v1(7452.5,3549.09) 7452.5,3531.62 7470.37,3513.75 7470.37,3500.98 U1.17@7470.64,3500.71
  Top Layer w20: R140.1@6122.28,2370.23 R142.2@6225.7,2370.23 C123.1@6329.12,2370.23 6330.47,2368.87 v9(6330.47,2324.09)
  Analog Signal w20: v9(6330.47,2324.09) 6430.03,2423.65 6430.03,3102.23 6580.73,3252.92 6580.73,3534.04 6715.8,3669.11 7332.48,3669.11 v1(7452.5,3549.09)
V_Sense_1: C152.1 R107.2 U2.11 | length 181.4
  Top Layer w14: U2.11@6980.9,2675.88 6983.48,2678.46 6983.48,2726.97 6998.4,2741.88 6998.4,2779.17 C152.1@7001.72,2782.49 R107.2@7067.88,2782.49
V_Sense_2: C108.1 R99.2 U2.10 | length 231.5
  Top Layer w14: U2.10@7030.9,2675.88 7030.9,2705.41 7065.51,2740.01 7092.67,2740.01 7134.17,2781.51 C108.1@7134.17,2782.49 R99.2@7200.33,2782.49
V_Sense_3: C98.1 R91.2 U2.9 | length 189.2
  Top Layer w14: U2.9@7080.9,2675.88 7080.9,2664.36 7085.71,2659.55 R91.2@7183.81,2659.55 C98.1@7183.81,2586.81
V_Sense_4: C89.1 R83.2 U2.8 | length 251.6
  Top Layer w14: U2.8@7080.9,2305.8 7080.9,2335.33 7171.13,2425.56 7171.13,2429.76 7182.83,2441.46 C89.1@7183.81,2441.46 R83.2@7183.81,2514.2
V_Sense_5: C101.1 J5.3 R102.2 TP32.1 U19.7 | length 534.7
  Top Layer w14: U19.7@7005.79,1865.26 U19.7@7008.34,1865.26 ; U19.7@7011.42,1868.34 U19.7@7008.34,1865.26 ; R102.2@7191.56,1938.57 C101.1@7109.32,1938.57 7102.82,1938.57 7084.82,1920.57 7084.82,1914.17 7035.92,1865.26 U19.7@7008.34,1865.26
  Top Layer w20: R102.2@7191.56,1938.57 R102.2@7192.33,1937.8 7193.06,1937.06 v1(7253.11,1937.06) 7270.82,1919.35 7315.37,1919.35 TP32.1@7319.07,1915.65
  Analog Signal w20: v1(7253.11,1937.06) 7266.39,1937.06 J5.3@7379.65,1823.8
V_Sense_6: C103.1 R95.2 U2.6 | length 330.7
  Top Layer w14: U2.6@6980.9,2305.8 6980.9,2276.27 6998.4,2258.77 7041.56,2215.61 7124.41,2215.61 7158.04,2181.99 7169.74,2170.29 R95.2@7169.74,2169.3 C103.1@7237.23,2169.3
V_Sense_7: C94.1 R86.2 U2.5 | length 247.5
  Top Layer w14: U2.5@6930.9,2305.8 6935.71,2300.99 6935.71,2268.2 7021.93,2181.99 7022.91,2181.99 7034.61,2170.29 R86.2@7034.61,2169.3 C94.1@7102.11,2169.3
V_Sense_8: C86.1 R3.2 U2.4 | length 213.4
  Top Layer w14: U2.4@6880.9,2305.8 6880.9,2276.27 6885.71,2271.46 6888.68,2271.46 6896.88,2263.26 6896.88,2171.91 R3.2@6899.49,2169.3 C86.1@6966.99,2169.3
VCC_TARGET: J1.3 JTAG.4 | length 308.8
  Bottom Layer w16: J1.3@7890.2,3757.49 7890.2,3762.63 7918.27,3790.7 7918.27,3791.41 8070.58,3943.72 JTAG.4@8070.58,3991.54
VCC_TOOL: J1.1 JTAG.2 | length 550.2
  Bottom Layer w16: J1.1@7890.2,3557.49 8170.58,3837.87 JTAG.2@8170.58,3991.54
pads on no net: FID1.1 FID2.1 FID3.1 H1.1 H2.1 H4.1 H5.0 H6.0 H8.0 JTAG.6 LBL1.0 U1.18 U1.38 U1.42 U1.43 U4.11@5837.81,1820.99 U4.11@5837.81,1866.27 U4.11@5837.81,1911.54 U4.11@5837.81,1956.82 U4.11@5837.81,2002.1 U4.11@5837.81,2047.37 U4.11@5883.09,1820.99 U4.11@5883.09,1866.27 U4.11@5883.09,1911.54 U4.11@5883.09,1956.82 U4.11@5883.09,2002.1 U4.11@5883.09,2047.37 U4.11@5928.36,1820.99 U4.11@5928.36,1866.27 U4.11@5928.36,1911.54 U4.11@5928.36,1956.82 U4.11@5928.36,2002.1 U4.11@5928.36,2047.37 U4.11@5973.64,1820.99 U4.11@5973.64,1866.27 U4.11@5973.64,1911.54 U4.11@5973.64,1956.82 U4.11@5973.64,2002.1 U4.11@5973.64,2047.37 U6.11@5560.68,2421.65 U6.11@5560.68,2466.93 U6.11@5560.68,2512.2 U6.11@5560.68,2557.48 U6.11@5605.95,2421.65 U6.11@5605.95,2466.93 U6.11@5605.95,2512.2 U6.11@5605.95,2557.48 U6.11@5651.23,2421.65 U6.11@5651.23,2466.93 U6.11@5651.23,2512.2 U6.11@5651.23,2557.48 U6.11@5696.5,2421.65 U6.11@5696.5,2466.93 U6.11@5696.5,2512.2 U6.11@5696.5,2557.48 U6.11@5741.78,2421.65 U6.11@5741.78,2466.93 U6.11@5741.78,2512.2 U6.11@5741.78,2557.48 U6.11@5787.05,2421.65 U6.11@5787.05,2466.93 U6.11@5787.05,2512.2 U6.11@5787.05,2557.48 U9.7 U11.7 U23.8 U23.9 U26.11@5016.72,2103.66 U26.11@5016.72,2148.94 U26.11@5016.72,2194.21 U26.11@5016.72,2239.49 U26.11@5062,2103.66 U26.11@5062,2148.94 U26.11@5062,2194.21 U26.11@5062,2239.49 U26.11@5107.28,2103.66 U26.11@5107.28,2148.94 U26.11@5107.28,2194.21 U26.11@5107.28,2239.49 U26.11@5152.55,2103.66 U26.11@5152.55,2148.94 U26.11@5152.55,2194.21 U26.11@5152.55,2239.49 U26.11@5197.83,2103.66 U26.11@5197.83,2148.94 U26.11@5197.83,2194.21 U26.11@5197.83,2239.49 U26.11@5243.1,2103.66 U26.11@5243.1,2148.94 U26.11@5243.1,2194.21 U26.11@5243.1,2239.49

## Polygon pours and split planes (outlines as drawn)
GND on Top Layer "NONET_L02_P-001" (solid, remove dead copper, pour order 408): 3375.63,4407.15 3375.63,349.88 8109.11,349.88 8955.57,1196.34 8955.57,4407.15
Charger_Vin on Top Layer "NONET_L02_P-001" (solid, pour order 377): 3377.25,2736.06 3377.25,1926.62 4154.43,1926.62 4154.43,2531.57 3949.94,2736.06
12Vcc on Top Layer "NONET_L02_P-001" (solid, pour order 373): 5375.14,2161.36 5345.76,2131.99 5345.76,2085.79 5390.49,2041.07 5446.02,2041.07 5498.33,1988.76 5587.44,1988.76 5595.57,1980.63 5595.57,1912.62 5653.39,1854.81 5727.62,1854.81 5754.65,1881.84 5754.65,2043.04 5710.92,2086.77 5710.92,2152.14 5701.69,2161.36
GND on Top Layer "NONET_L02_P-001" (solid, pour order 276): 8279.52,1393.62 8241.37,1355.47 8241.37,1340.47 8297.53,1284.31 8413.81,1284.31 8504.58,1375.09 8504.59,1392.77 8481.86,1415.49 8398.7,1415.49 8376.83,1393.62
GND on Top Layer "NONET_L02_P-001" (solid, pour order 280): 6188.76,2629.86 6170.78,2611.89 6170.78,2431.97 6188.08,2414.68 6363.86,2414.68 6381.09,2431.92 6381.09,2608.39 6359.62,2629.86
12Vcc on Top Layer "NONET_L02_P-001" (solid, pour order 326): 7927.47,1327.26 7788.92,1188.71 7788.92,1151.81 7797.36,1143.36 7842.09,1143.36 7979.39,1280.66 7979.39,1312.25 7964.38,1327.26
NetLoad_1 on Top Layer "NONET_L02_P-001" (solid, pour order 209): 4209.46,4364.27 3394.58,4364.27 3394.58,3274.01 3808.18,3274.01 3939.7,3405.53 3939.7,3639.33 4074.3,3773.93 4209.46,3773.93
NetQ49_2 on Top Layer "NONET_L02_P-001" (solid, pour order 210): 8338.05,3765.64 8301.14,3728.73 8301.14,3650.75 8416.04,3535.85 8505.98,3535.85 8545.49,3575.36 8545.49,3710.02 8489.86,3765.64
NetR8_1 on Top Layer "NONET_L02_P-001" (solid, pour order 224): 6062.35,932.51 5987.12,857.28 5987.12,740.77 6243.92,740.77 6269.5,766.35 6269.5,915.02 6252.01,932.51
Batt5_21V on Top Layer "NONET_L02_P-001" (solid, pour order 232): 7013.69,857.86 7013.69,619.14 7101.8,531.04 7500.43,531.04 7574.64,605.25 7574.64,697.95 7578.48,697.95 7639.37,758.85 7639.37,826.32 7610.84,854.84 7512.1,854.84 7419.94,762.69 7321.75,762.69 7226.57,857.86
Batt7_29V4 on Top Layer "NONET_L02_P-001" (solid, pour order 233): 6247.3,732.61 5918.96,732.61 5918.96,617.57 6079.3,457.23 6512.44,457.23 6512.44,457.76 6514.87,460.2 6514.87,867.07 6465.6,867.07 6465.43,866.91 6465.51,866.82 6465.51,798.91 6427.65,761.05 6275.73,761.05
Batt2_8V4 on Top Layer "NONET_L02_P-001" (solid, pour order 234): 8776.75,2588.6 8776.75,1456.58 8505.63,1185.46 8505.63,912.08 8585.75,831.95 8600.55,831.95 8632.06,863.46 8945.87,1177.27 8945.87,2589.86
Batt_out on Top Layer "NONET_L02_P-001" (solid, pour order 237): 5786.07,705.74 5786.07,338.18 8106.88,338.18 8333.99,565.29 8222.49,676.8 8138.17,676.8 7910.45,449.07 6010.43,455.2 5888.39,705.74
Batt6_25V2 on Top Layer "NONET_L02_P-001" (solid, pour order 236): 6851,706.17 6851,451.21 7903.77,451.21 8135.13,682.57 8286.17,682.57 8344.2,740.6 8344.2,775.74 8303.08,816.87 8143.84,816.87 7872.53,545.56 7113.37,545.56 6952.77,706.17
Batt4_16V8 on Top Layer "NONET_L02_P-001" (solid, pour order 235): 7916.5,756.73 7916.5,591.05 8149.37,823.92 8412.83,823.92 8499.86,910.95 8499.86,1186.83 8776.75,1463.72 8776.75,1575.21 8643.92,1575.21 8643.92,1437.9 7962.75,756.73
Batt4_16V8 on Top Layer "NONET_L02_P-001" (solid, pour order 392): 7647.7,757.73 7550.25,660.28 7550.25,586.43 7940.18,586.43 7940.18,757.73
NetQ49_3 on Top Layer "NONET_L02_P-001" (solid, pour order 406): 8282.75,3555.09 8175.03,3447.38 8175.03,3298.8 8172.25,3296.01 8199.17,3269.08 8244.21,3269.08 8244.21,3271.87 8360.41,3388.07 8360.41,3537.33 8342.65,3555.09
NetQ14_3 on Top Layer "NONET_L02_P-001" (solid, pour order 405): 8214.95,3022.93 8202.17,3010.15 8202.17,2885.3 8228.71,2858.75 8331.94,2858.75 8355.53,2835.16 8355.53,2786.98 8385.52,2757 8414.52,2757 8442.05,2784.53 8442.05,2941.39 8360.5,3022.93
NetQ9_3 on Top Layer "NONET_L02_P-001" (solid, pour order 404): 8206.6,2566.67 8193.82,2553.89 8193.82,2429.03 8220.37,2402.49 8323.59,2402.49 8347.19,2378.89 8347.19,2330.72 8377.17,2300.74 8406.18,2300.74 8433.7,2328.26 8433.7,2485.13 8352.16,2566.67
NetQ5_3 on Top Layer "NONET_L02_P-001" (solid, pour order 403): 8215.78,2113.97 8203,2101.19 8203,1976.33 8229.54,1949.79 8332.77,1949.79 8356.36,1926.19 8356.36,1878.02 8386.35,1848.03 8415.35,1848.03 8442.88,1875.56 8442.88,2024.68 8353.6,2113.97
Batt2_8V4 on Top Layer "NONET_L02_P-001" (solid, pour order 397): 8518.07,2870.1 8604.75,2956.78 8859.19,2956.78 8945.87,2870.1 8945.87,2431.88 8434.03,2431.88 8434.03,2578.43 8546.88,2578.43 8568.35,2599.89 8568.35,2747.1 8507.01,2808.44 8456.92,2808.44 8449.07,2816.29 8449.07,2870.1
Batt1_4V2 on Top Layer "NONET_L02_P-001" (solid, pour order 400): 8414.72,3455.66 8414.72,3081.1 8459.05,3036.77 8459.05,2878.57 8598.71,2878.57 8640.95,2836.34 8945.87,2836.34 8945.87,3455.66
Batt3_12V6 on Top Layer "NONET_L02_P-001" (solid, pour order 395): 8433.08,2432.66 8433.08,2359.44 8448.92,2343.6 8499.01,2343.6 8560.35,2282.26 8560.35,2135.05 8538.88,2113.59 8471.41,2113.59 8456.34,2098.52 8456.34,1964.97 8573.83,1964.97 8605,1933.8 8825.55,1933.8 8825.55,2432.66
Batt4_16V8 on Top Layer "NONET_L02_P-001" (solid, pour order 394): 8445.08,1957.23 8445.08,1893.3 8510.8,1893.3 8557.29,1846.8 8557.29,1545.33 8778.05,1545.33 8778.05,1929.71 8605.32,1929.71 8577.81,1957.23
Batt_out on Top Layer "NONET_L02_P-001" (solid, pour order 393): 3369.77,1463.65 3369.77,340.64 4630.53,340.64 4630.53,1123.97 4518.37,1123.97 4461.77,1067.37 4387.08,1067.37 4255.38,1199.07 3927.91,1199.07 3663.33,1463.65
NetQ1_3 on Top Layer "NONET_L02_P-001" (solid, pour order 391): 7662.57,925.01 7644.66,907.1 7644.66,764.83 7946.19,764.83 7946.19,882.29 7903.48,925.01
Batt_out on Top Layer "NONET_L02_P-001" (solid, pour order 238): 5911.1,870.89 5911.1,799.01 5854.61,742.52 5729.26,742.52 5635.18,648.43 5635.18,344.49 5977.28,344.49 5977.28,870.89
NetQ2_3 on Top Layer "NONET_L02_P-001" (solid, pour order 388): 5874.92,961.64 5874.92,871.86 6171.02,871.86 6171.02,1076.25 6148.74,1098.53 6026.78,1098.53 5992.45,1064.21
NetQ12_3 on Top Layer "NONET_L02_P-001" (solid, pour order 390): 6943.73,955.79 6943.73,866.02 7239.83,866.02 7239.83,1070.41 7217.55,1092.69 7095.59,1092.69 7061.26,1058.36
NetQ7_3 on Top Layer "NONET_L02_P-001" (solid, pour order 389): 6420.13,965 6420.13,875.23 6716.23,875.23 6716.23,1079.62 6693.95,1101.9 6571.99,1101.9 6537.66,1067.57
Batt6_25V2 on Top Layer "NONET_L02_P-001" (solid, pour order 206): 7040.12,726.06 6991.35,677.29 6991.35,567.66 7040.12,519.86 7040.12,460.2 6523.03,460.2 6523.03,870.89 6687.86,870.89 6801.02,757.73 6946.95,757.73 6987.26,798.05 6987.26,859.37 7040.12,859.37
NetC25_1 on Top Layer "NONET_L02_P-001" (solid, pour order 239): 5707.87,3153.2 5640.03,3085.36 5640.03,2840.97 5650.04,2830.96 5650.04,2680.88 5657.66,2673.26 5797.5,2673.26 5807.23,2682.99 5807.23,2747.83 5788.82,2766.24 5750.82,2766.24 5737.54,2779.51 5737.54,3004.5 5781.09,3048.05 6241.59,3048.05 6252,3058.45 6252,3191.15 5745.83,3191.15
3.3V on Top Layer "NONET_L02_P-001" (solid, pour order 241): 5291.35,2931.53 5291.35,2673.2 5420.26,2673.2 5420.26,2931.53
NetC33_1 on Top Layer "NONET_L02_P-001" (solid, pour order 366): 5188.39,2905.84 5157.94,2875.39 5157.94,2638.26 5172.36,2623.84 5172.36,2452.22 5121.62,2452.22 5109.17,2439.78 5109.17,2365.99 5125.6,2349.56 5254.98,2349.56 5282.73,2377.31 5282.73,2875.22 5252.11,2905.84
NetC11_1 on Top Layer "NONET_L02_P-001" (solid, pour order 368): 6030.29,1959.08 6017.24,1946.02 6017.24,1808.5 6209,1808.5 6359.57,1959.08 6455.13,1959.08 6455.13,2031.27 6427.47,2060.32 6353.88,2060.32 6303.35,2009.79 6209,2009.79 6158.28,1959.08
NetQ18_5 on Top Layer "NONET_L02_P-001" (solid, pour order 385): 4328.11,2708.61 4328.11,2552.24 4373.93,2506.42 4373.93,1996.23 4411.56,1958.6 4651.71,1958.6 4660.09,1966.98 4660.09,2652.01 4603.5,2708.61
NetD4_2 on Top Layer "NONET_L02_P-001" (solid, pour order 384): 4186.69,2486.36 4186.69,2227.47 4360.49,2227.47 4360.49,2486.36
NetLoad_2 on Top Layer "NONET_L02_P-001" (solid, pour order 374): 4076.8,3765.77 3947.86,3636.83 3947.86,3400.75 3812.96,3265.85 3369.09,3265.85 3369.09,2905.22 4050.44,2905.22 4479.61,3334.39 4479.61,3663.46 4377.3,3765.77
0V6 on Top Layer "NONET_L02_P-001" (solid, pour order 381): 5069.95,3203.5 5041.32,3174.87 5041.32,2993.18 5067.02,2967.48 5130.8,2967.48 5152.94,2989.62 5152.94,3175.84 5125.28,3203.5
NetJ4_2 on Top Layer "NONET_L02_P-001" (solid, pour order 379): 5782.02,4003.14 5775.3,3996.42 5775.3,3886.21 5750.5,3861.41 5750.5,3802.33 5752.5,3802.33 5777.07,3777.76 5845.37,3777.76 5907.38,3839.77 5958.15,3839.77 5984.25,3865.87 5984.25,3930.44 5955.29,3959.4 5886.96,3959.4 5843.22,4003.14
G2 on Top Layer "NONET_L02_P-001" (solid, pour order 376): 4023.47,1742.3 4009.77,1728.6 4009.77,1654.07 4051.41,1612.43 4174.94,1612.43 4228.93,1558.43 4295.63,1558.43 4330.22,1593.02 4330.22,1767.36 4319.28,1778.3 4276.22,1778.3 4240.23,1742.3
5Vcc on Top Layer "NONET_L02_P-001" (solid, pour order 371): 5550.32,2311.9 5524.94,2286.52 5524.94,2171.21 5754.81,2171.21 5768.58,2156.61 6329.82,2156.61 6455.16,2031.27 6455.16,1975.3 6646.11,1975.3 6779.51,2108.71 6779.51,2230.53 6806.09,2257.1 6806.09,2352.8 6795.08,2363.8 6767.43,2363.8 6756.07,2352.44 6756.07,2271.9 6732.62,2248.45 5910.52,2248.45 5888.85,2226.78 5767.56,2226.78 5750.26,2244.08 5750.26,2297.07 5735.43,2311.9
12V on Top Layer "NONET_L02_P-001" (solid, pour order 352): 4931.43,1304.24 4880.16,1355.52 4880.16,1870.17 4905.56,1895.57 5184.78,1895.57 5207.24,1918.03 5207.24,1974.03 5180.36,2000.92 4839.42,2000.92 4715,1876.5 4715,1156.43 4847.43,1024 5270.09,1024 5326.42,1080.33 5464.35,1080.33 5477.25,1093.24 5477.25,1157.49 5436.57,1198.17 5436.57,1251.2 5383.53,1304.24
"Net12V Supply_1" on Top Layer "NONET_L02_P-001" (solid, pour order 367): 4850.16,1019.07 4850.16,894.65 5036.95,894.65 5162.86,768.74 5162.86,622.06 5238.97,545.95 5347.4,545.95 5384.68,583.23 5384.68,904.6 5270.21,1019.07
NetC9_1 on Top Layer "NONET_L02_P-001" (solid, pour order 359): 4897.48,1887.48 4883.9,1873.91 4883.9,1662.66 4908.25,1638.32 5089.2,1638.32 5107.33,1656.44 5394.64,1656.44 5437.03,1698.83 5437.03,1782.99 5473.87,1819.83 5473.87,1886.65 5473.87,2004.77 5444.29,2034.35 5389.59,2035.19 5368.72,2018.07 5370.46,1938.31 5327.81,1887.48
3.3V on Top Layer "NONET_L02_P-001" (solid, pour order 251): 7320.56,3246.76 7271.39,3197.59 7271.39,3129.19 7249.22,3107.01 7249.22,3076.7 7261.89,3064.03 7322.52,3064.03 7332.93,3074.43 7337.81,3079.32 7337.81,3245.36 7336.41,3246.76
3.3V on Top Layer "NONET_L02_P-001" (solid, pour order 273): 7545.98,3248.44 7541.28,3243.73 7541.28,3221.39 7584.17,3178.5 7744.67,3178.5 7756.59,3190.42 7756.59,3220.22 7728.36,3248.44
NetQ41_3 on Top Layer "NONET_L02_P-001" (solid, pour order 274): 7865.34,1162.52 7804.13,1101.31 7804.13,1037.56 7954.33,887.36 8087.94,887.36 8409.56,1208.98 8409.56,1250.79 8386.44,1273.91 8290.54,1273.91 8219.12,1345.33 8169.39,1345.33 7986.58,1162.52
5Vcc on Top Layer "NONET_L02_P-001" (solid, pour order 281): 7627.74,2301.91 7614.88,2289.05 7614.88,2136.95 7596.03,2118.1 7596.03,2104.37 7605.53,2094.86 7630.36,2094.86 7644.62,2109.12 7664.16,2109.12 7679.48,2124.44 7679.48,2167.22 7668.39,2178.31 7668.39,2288.18 7654.65,2301.91
2.5Vref on Top Layer "NONET_L02_P-001" (solid, pour order 283): 7571.73,2296.77 7565.25,2290.28 7565.25,2190.99 7534.45,2160.19 7534.45,2097.38 7540.12,2091.71 7551.87,2091.71 7565.65,2105.49 7594.02,2105.49 7614.28,2125.75 7614.28,2282.09 7599.6,2296.77
2.5Vref on Top Layer "NONET_L02_P-001" (solid, pour order 284): 7688,2297.73 7669.35,2279.08 7669.35,2178.29 7679.92,2167.72 7679.92,2124.23 7669.97,2114.28 7669.97,2103.71 7681.78,2091.89 7694.53,2091.89 7709.46,2106.82 7737.13,2106.82 7755.47,2125.16 7755.47,2166.21 7727.8,2193.88 7727.8,2280.97 7711.04,2297.73
2.5Vref on Top Layer "NONET_L02_P-001" (solid, pour order 285): 7675.5,2793.86 7659.54,2777.89 7609.29,2777.89 7570.79,2739.39 7570.79,2598.99 7580.18,2589.6 7603.66,2589.6 7623.85,2609.79 7623.85,2699.01 7637.47,2712.63 7648.74,2712.63 7660.95,2700.42 7660.95,2600.4 7677.85,2583.5 7706.49,2583.5 7718.7,2595.7 7718.7,2699.01 7701.33,2716.38 7701.33,2778.62 7686.09,2793.86
2.5Vref on Top Layer "NONET_L02_P-001" (solid, pour order 286): 6450.34,1771.1 6442.36,1763.11 6442.36,1746.41 6460.59,1728.18 6460.59,1691.11 6485.46,1666.24 6512.77,1666.24 6533.17,1645.84 6642.6,1645.84 6654.22,1657.46 6654.22,1671.6 6630.32,1695.5 6540.09,1695.5 6528.1,1707.49 6528.1,1716.94 6544.24,1733.09 6653.26,1733.09 6665.97,1745.79 6665.97,1770.22 6645.61,1790.58 6543.46,1790.58 6523.98,1771.1
5Vcc on Top Layer "NONET_L02_P-001" (solid, pour order 296): 6962.8,1745.79 6944.1,1727.09 6944.1,1705.7 6963.29,1686.5 7115.21,1686.5 7132.76,1704.05 7132.76,1723.8 7147.57,1738.61 7147.57,1755.61 7138.8,1764.38 7120.7,1764.38 7102.11,1745.79
2.5Vref on Top Layer "NONET_L02_P-001" (solid, pour order 307): 6957.58,1797.01 6945.64,1785.07 6945.64,1764.81 6962.9,1747.56 7103.75,1747.56 7132.55,1776.35 7132.55,1790.44 7148.51,1806.4 7148.51,1824.24 7141.31,1831.44 7081.84,1831.44 7047.41,1797.01
2.5Vref on Top Layer "NONET_L02_P-001" (solid, pour order 308): 6948.03,1684.58 6943.43,1679.98 6943.43,1642.94 6949.47,1636.9 7060.13,1636.9 7084.39,1612.64 7118.27,1612.64 7129.14,1623.51 7129.14,1654.05 7147.13,1672.03 7147.13,1686.67 7137.51,1696.29 7125.38,1696.29 7113.67,1684.58
3.3V_2 on Top Layer "NONET_L02_P-001" (solid, pour order 323): 6795.78,2984.07 6767.27,2955.56 6767.27,2793.14 6853.61,2706.79 6853.61,2634.54 6869.75,2618.4 6897.42,2618.4 6907.04,2628.02 6907.04,2742.89 6882.98,2766.95 6882.98,2970.32 6869.23,2984.07
1.89V on Top Layer "NONET_L02_P-001" (solid, pour order 325): 6644.64,3446.33 6644.64,3290.04 6546.08,3191.49 6255.22,3191.49 6255.22,3059.53 6280.19,3034.56 6583.01,3034.56 6717.23,3168.77 6717.23,3446.33
NetQ36_3 on Top Layer "NONET_L02_P-001" (solid, pour order 334): 8012.62,1477.65 7943.72,1408.75 7943.72,1361.37 7972.15,1332.94 8049.02,1332.94 8113.25,1397.17 8113.25,1419.69 8055.29,1477.65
